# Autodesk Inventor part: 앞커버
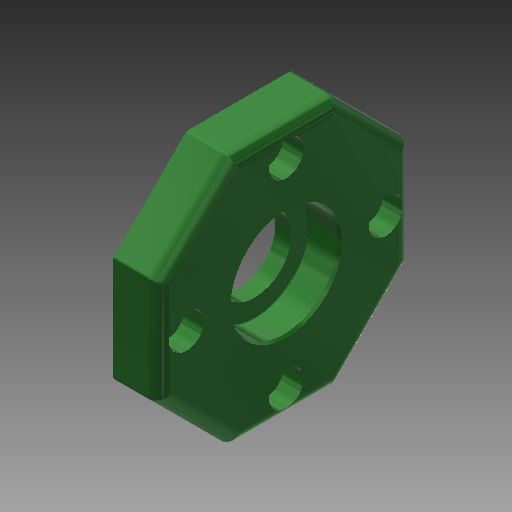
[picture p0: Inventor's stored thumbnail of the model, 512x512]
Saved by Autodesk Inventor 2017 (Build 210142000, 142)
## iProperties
Created: 2015-11
Part Number: 앞커버
Material: 알루미늄 6061
Document SubType Name: Modeling
Designer: mduedu
Density: 1 g/cm^3
Appearance: 매끄러움 - 짙은 산림 녹색
Author: mduedu
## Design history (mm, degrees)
sketch "스케치5" dims "d66" = 58
  geometry: L1 (12.012, 29)-(29, 12.012); L2 (29, 12.012)-(29, -12.012); L3 (29, -12.012)-(12.012, -29); L4 (12.012, -29)-(-12.012, -29); L5 (-12.012, -29)-(-29, -12.012); L6 (-29, -12.012)-(-29, 12.012); L7 (-29, 12.012)-(-12.012, 29); L8 (-12.012, 29)-(12.012, 29); 4 further points
  constraints: 16 end point, 2 coincident, 2 vertical alignment, 1 midpoint, 19 other
extrude "돌출2" new body sketch "스케치5" distance "d67" = 11; taper "d68" = 0 deg
sketch "스케치6"
  geometry: C1 r 16 at (0, 0); 1 further point
  constraints: 1 centre point, 1 coincident
  dimensions: "d69" = 32 diameter of C1
extrude "돌출3" join sketch "스케치6" distance "d70" = 3; taper "d71" = 0 deg
hole "구멍7" diameter "d98" = 28; stored, may be unused: countersink angle "d102" = 90 deg, drill point angle "d104" = 0 deg; dims "d99" = 6, "d100" = 4, "d101" = 2, "d103" = 3, "d145" = 10, "d146" = 10
hole "구멍8" diameter "d107" = 25; stored, may be unused: countersink angle "d111" = 90 deg, drill point angle "d113" = 0 deg; dims "d108" = 6, "d109" = 4, "d110" = 2, "d112" = 7.3, "d143" = 10, "d144" = 10
hole "구멍9" diameter "d116" = 17; stored, may be unused: countersink angle "d120" = 90 deg, drill point angle "d122" = 0 deg; dims "d114" = 10, "d115" = 10, "d117" = 6, "d118" = 4, "d119" = 2, "d121" = 7.7
chamfer "모따기2" distance "d123" = 0.6; stored, may be unused: second distance "d124" = 2, angle "d125" = 30 deg
fillet "모깎기11" dims "d126" = 0.3
fillet "모깎기12" dims "d127" = 1
fillet "모깎기13" dims "d128" = 3
fillet "모깎기14" dims "d129" = 3
fillet "모깎기15" dims "d130" = 0.3
sketch "스케치8" dims "d131" = 46
  geometry: 3 further points
  constraints: 2 vertical alignment, 1 coincident, 2 other
hole "구멍10" sketch "스케치8" at (0, 23) diameter "d132" = 4.5; stored, may be unused: countersink angle "d136" = 90 deg, drill point angle "d138" = 0 deg; dims "d133" = 6, "d134" = 8, "d135" = 4.6, "d137" = 7.7
node "솔리드2"
pattern_circular "원형 패턴4" dims angle "d140" = 360 deg
